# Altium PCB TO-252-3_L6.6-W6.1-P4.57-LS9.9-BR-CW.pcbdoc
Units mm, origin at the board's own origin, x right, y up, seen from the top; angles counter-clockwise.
Board outline 24.15 x 19.7 mm, 2 copper layers (Top Layer, Bottom Layer), stack 0 mm thick; 1 components, 0 nets, 3 pads, 0 vias.
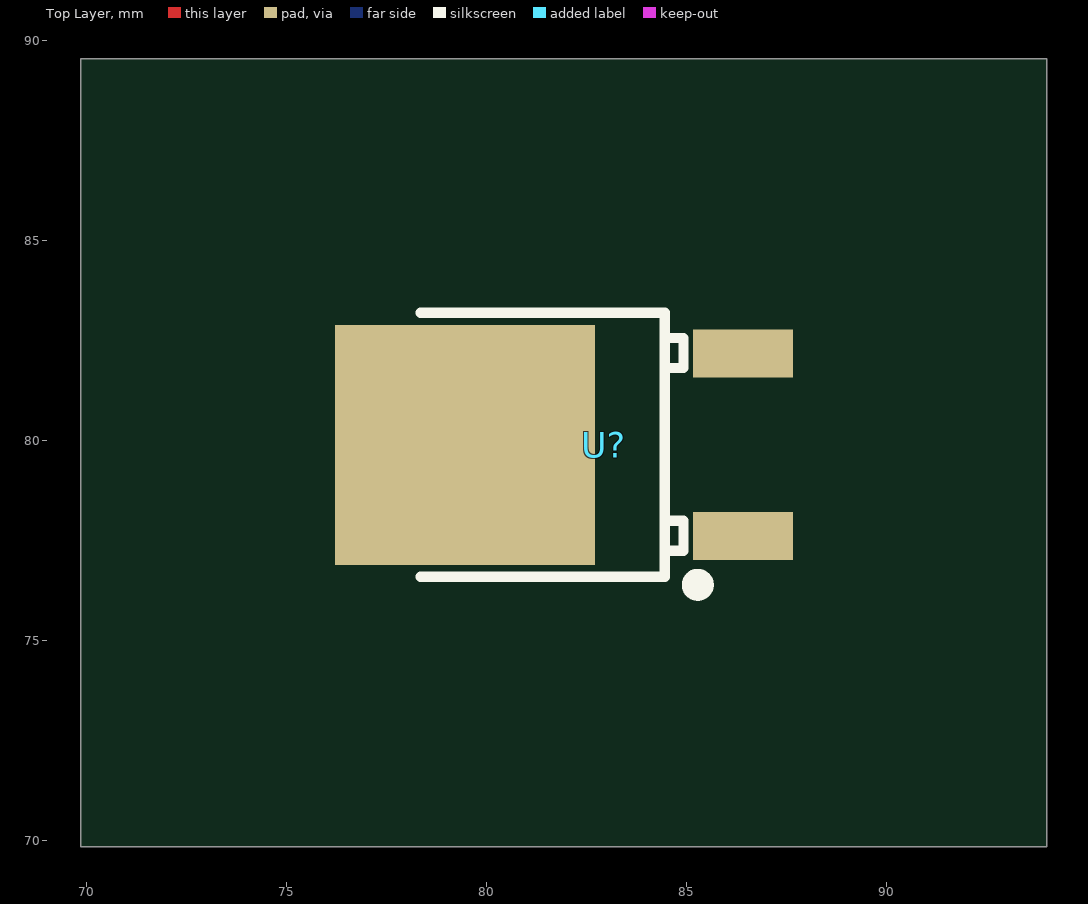
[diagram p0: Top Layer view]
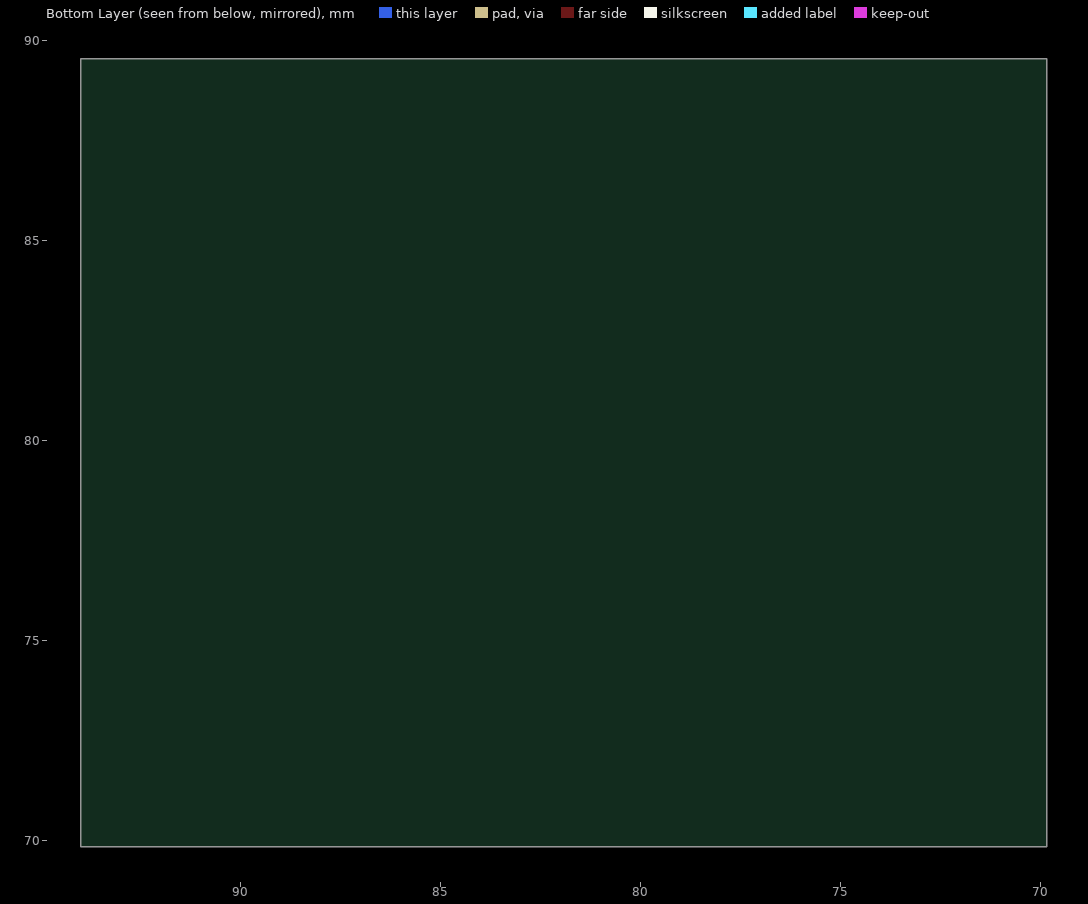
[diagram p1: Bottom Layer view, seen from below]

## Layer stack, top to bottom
Top Layer: signal copper (thickness not stored)
Bottom Layer: signal copper (thickness not stored)

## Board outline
94,69.85 69.85,69.85 69.85,89.55 94,89.55

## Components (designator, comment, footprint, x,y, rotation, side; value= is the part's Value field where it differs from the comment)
U? "" TO-252-3_L6.6-W6.1-P4.57-LS9.9-BR-CW 82.925,79.9 r0 top

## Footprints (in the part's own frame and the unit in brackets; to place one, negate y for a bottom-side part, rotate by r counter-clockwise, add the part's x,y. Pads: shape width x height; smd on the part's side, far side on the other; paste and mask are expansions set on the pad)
TO-252-3_L6.6-W6.1-P4.57-LS9.9-BR-CW [mm]
  rect 2.5x1.2 smd paste+0 mask+0.05: 1(3.475,-2.286) 3(3.475,2.286)
  rect 6.5x6 smd paste+0 mask+0.05: 2(-3.475,0)
  silkscreen extent -4.57,-3.7 2.55,3.3

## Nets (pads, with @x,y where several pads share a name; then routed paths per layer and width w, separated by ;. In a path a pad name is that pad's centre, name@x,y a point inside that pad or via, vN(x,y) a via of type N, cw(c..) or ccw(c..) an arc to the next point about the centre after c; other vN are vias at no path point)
pads on no net: U?.1 U?.2 U?.3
